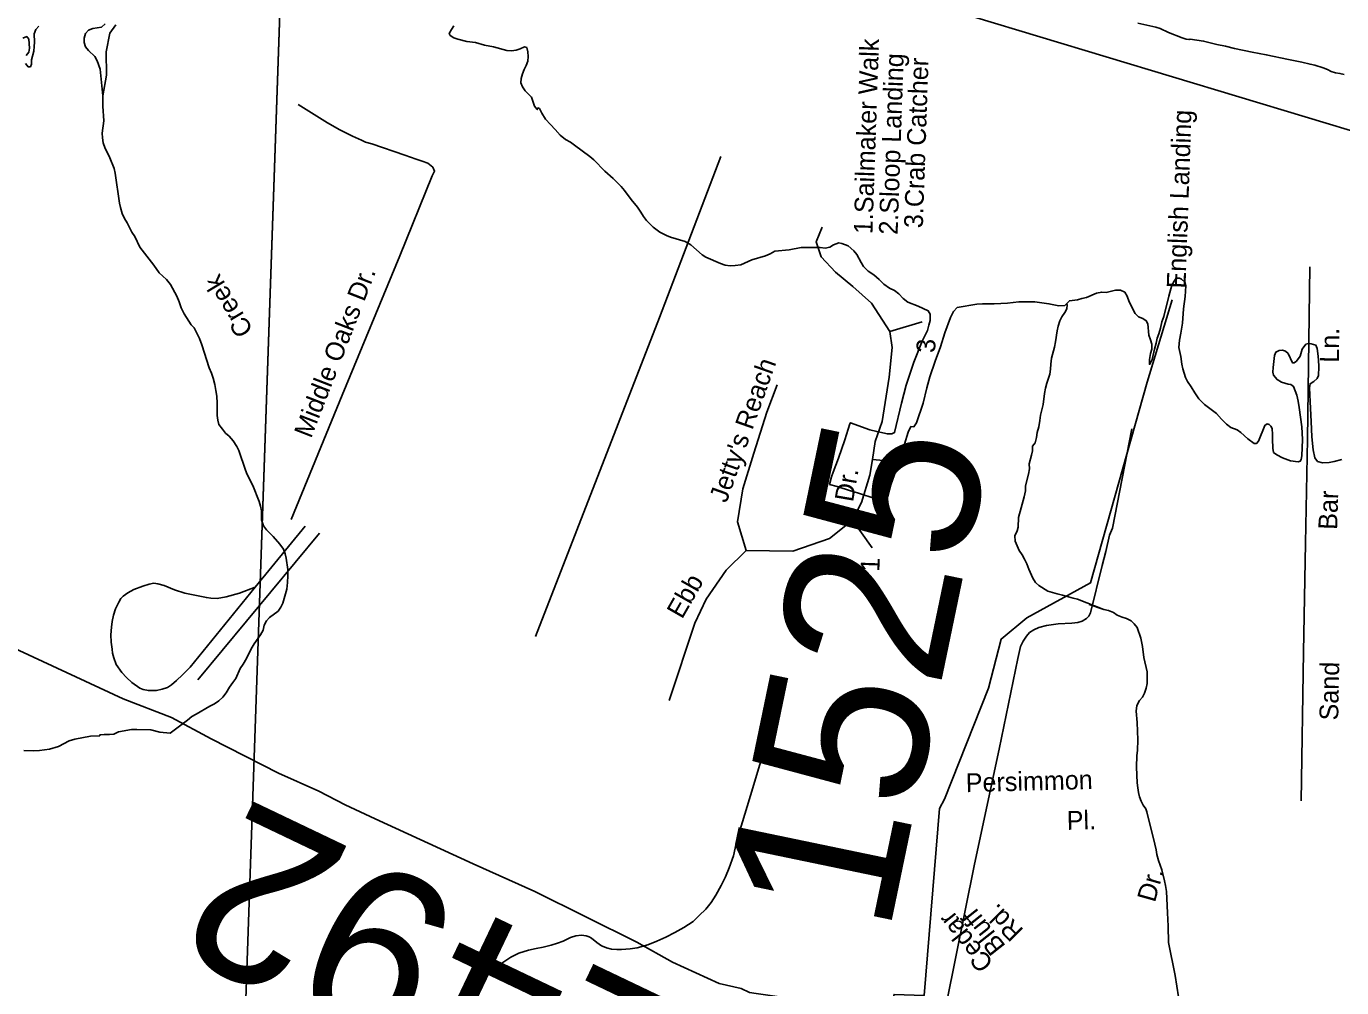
# Model space of a CAD drawing. Extents: x 2308163 to 2335412, y -96774 to 125428.
# Drawn here: x 2326033 to 2326126.4, y 123212.4 to 123280.7 of the extents above; entities that cross this region are included whole.
import ezdxf

# ---------------------------------------------------------------- set-up
doc = ezdxf.new("R2010")
doc.units = 0
for name, color, linetype in [('Old_Level_10', 7, 'Continuous'), ('Old_Level_21', 7, 'Continuous'), ('Old_Level_32', 7, 'Continuous'), ('Old_Level_35', 7, 'Continuous'), ('Old_Level_50', 7, 'Continuous'), ('Old_Level_59', 7, 'Continuous'), ('Old_Level_60', 7, 'Continuous'), ('Old_Level_61', 7, 'Continuous'), ('Old_Level_63', 7, 'Continuous'), ('Old_Level_8', 7, 'Continuous')]:
    doc.layers.add(name, color=color, linetype=linetype)

msp = doc.modelspace()

# ---------------------------------------------------------------- linework, layer by layer
at = {"layer": 'Old_Level_32'}
for points in [[(2326098.302, 123211.329), (2326100.302, 123221.192), (2326102.047, 123229.355), (2326103.38, 123235.79), (2326103.562, 123236.637), (2326103.76, 123237.018), (2326103.985, 123237.385), (2326104.197, 123237.64), (2326104.502, 123237.834), (2326104.855, 123237.989), (2326105.4, 123238.139), (2326106.239, 123238.249), (2326107.218, 123238.294), (2326107.631, 123238.343), (2326107.93, 123238.438), (2326108.242, 123238.639), (2326108.408, 123238.8), (2326108.54, 123239.04), (2326109.352, 123242.385), (2326109.62, 123243.386), (2326109.893, 123244.542), (2326110.104, 123245.039), (2326111.475, 123252.101)], [(2326024.035, 123240.511), (2326029.487, 123237.988), (2326032.481, 123236.361), (2326039.85, 123232.926)], [(2326039.85, 123232.926), (2326043.283, 123231.597), (2326046.116, 123230.094), (2326050.884, 123227.65), (2326053.752, 123226.388), (2326055.613, 123225.408), (2326057.739, 123224.419), (2326064.699, 123221.235), (2326069.083, 123219.252), (2326076.335, 123215.667), (2326078.862, 123214.252)], [(2326078.862, 123214.252), (2326082.17, 123212.726), (2326083.743, 123212.381), (2326084.315, 123212.102), (2326084.798, 123212.021), (2326086.295, 123211.817), (2326091.178, 123211.284), (2326094.057, 123211.281), (2326095.252, 123211.24)]]:
    msp.add_lwpolyline(points, dxfattribs=at)
at = {"layer": 'Old_Level_35'}
for p, q in [((2326052.788, 123245.192), (2326049.226, 123240.851)), ((2326045.168, 123234.282), (2326053.79, 123244.684))]:
    msp.add_line(p, q, dxfattribs=at)
for points in [[(2326051.779, 123245.667), (2326055.406, 123254.478), (2326059.506, 123264.378), (2326061.803, 123270.052), (2326061.968, 123270.373), (2326061.853, 123270.659), (2326061.499, 123270.95), (2326061.092, 123271.081), (2326060.651, 123271.219), (2326059.844, 123271.521), (2326057.508, 123272.309), (2326057.061, 123272.44), (2326056.781, 123272.572), (2326056.14, 123272.868), (2326055.251, 123273.303), (2326054.37, 123273.805), (2326052.291, 123275.114)], [(2326069.135, 123237.36), (2326077.941, 123259.987), (2326082.281, 123271.427)], [(2326078.622, 123232.814), (2326080.432, 123238.295), (2326081.245, 123240.002), (2326082.675, 123242.064), (2326084.081, 123243.448), (2326087.4, 123243.409), (2326089.996, 123244.3), (2326091.626, 123245.601), (2326092.273, 123246.861), (2326092.868, 123248.801), (2326093.058, 123249.925), (2326093.253, 123251.201), (2326093.754, 123252.616), (2326094.24, 123255.767), (2326094.464, 123257.87), (2326094.276, 123259.008), (2326092.987, 123261.013), (2326091.67, 123262.19), (2326090.422, 123263.213), (2326089.403, 123264.304), (2326089.063, 123265.371), (2326089.476, 123266.413)], [(2326123.486, 123225.688), (2326123.66, 123236.248), (2326123.808, 123243.969), (2326123.944, 123251.358), (2326124.116, 123263.59)], [(2326094.276, 123259.008), (2326096.586, 123259.687)], [(2326084.081, 123243.448), (2326083.472, 123245.505), (2326083.854, 123247.83), (2326084.621, 123250.367), (2326085.551, 123253.276), (2326086.297, 123255.211)], [(2326093.058, 123249.925), (2326094.875, 123249.75)], [(2326091.626, 123245.601), (2326093.033, 123243.659)], [(2326049.226, 123240.851), (2326044.617, 123235.192), (2326044.074, 123234.636), (2326043.656, 123234.241), (2326043.285, 123233.919), (2326043.013, 123233.738), (2326042.627, 123233.616), (2326042.214, 123233.528), (2326041.648, 123233.518), (2326041.288, 123233.603), (2326041.041, 123233.688), (2326040.479, 123234.085), (2326040.091, 123234.443), (2326039.763, 123234.808), (2326039.354, 123235.379), (2326039.185, 123235.851), (2326039.11, 123236.177), (2326039.082, 123236.463), (2326039.006, 123236.949), (2326038.99, 123237.469), (2326039.034, 123238.008), (2326039.085, 123238.415), (2326039.17, 123238.868), (2326039.314, 123239.315), (2326039.551, 123239.796), (2326039.697, 123240.064), (2326039.862, 123240.224), (2326040.194, 123240.459), (2326040.606, 123240.694), (2326041.264, 123240.924), (2326041.71, 123241.073), (2326042.036, 123241.141), (2326042.323, 123241.096), (2326042.763, 123240.965), (2326043.504, 123240.675), (2326044.231, 123240.439), (2326045.065, 123240.264), (2326045.765, 123240.114), (2326046.085, 123240.076), (2326046.525, 123240.064), (2326047.177, 123240.168), (2326048.122, 123240.432), (2326049.226, 123240.851)], [(2326085.54, 123229.815), (2326084.964, 123227.96), (2326084.564, 123226.625), (2326083.417, 123222.876), (2326083.189, 123221.782), (2326082.887, 123220.935), (2326082.624, 123220.294), (2326082.307, 123219.679), (2326081.944, 123219.011), (2326081.607, 123218.49), (2326081.23, 123218.008), (2326080.752, 123217.546), (2326080.315, 123217.138), (2326079.651, 123216.708), (2326079.02, 123216.345), (2326078.388, 123216.022), (2326077.737, 123215.726), (2326077.099, 123215.47), (2326076.36, 123215.266), (2326075.841, 123215.19), (2326075.228, 123215.147), (2326074.915, 123215.139), (2326074.536, 123215.164), (2326074.169, 123215.255), (2326073.996, 123215.334)], [(2326073.996, 123215.334), (2326073.821, 123215.413), (2326073.487, 123215.638), (2326073.113, 123215.949), (2326072.939, 123216.042), (2326072.732, 123216.114), (2326072.405, 123216.152), (2326071.999, 123216.124), (2326071.627, 123216.002), (2326071.095, 123215.733), (2326070.683, 123215.584), (2326070.244, 123215.449), (2326069.665, 123215.319), (2326069.173, 123215.21), (2326068.64, 123215.107), (2326067.955, 123214.884), (2326067.37, 123214.608), (2326066.746, 123214.172), (2326066.248, 123213.823), (2326065.917, 123213.542)]]:
    msp.add_lwpolyline(points, dxfattribs=at)
at = {"layer": 'Old_Level_50'}
msp.add_lwpolyline([(2326094.207, 123210.48), (2326094.59, 123211.958), (2326096.736, 123211.884), (2326097.816, 123225.143), (2326098.172, 123225.819), (2326101.298, 123233.695), (2326102.199, 123237.179), (2326104.009, 123238.679), (2326108.528, 123241.157), (2326112.565, 123255.395), (2326114.338, 123261.258)], dxfattribs=at)
at = {"layer": 'Old_Level_59'}
msp.add_line((2326113.092, 123222.623), (2326112.543, 123224.913), dxfattribs=at)
for points in [[(2326038.407, 123275.731), (2326038.405, 123274.994), (2326038.49, 123273.939), (2326038.365, 123273.085), (2326038.392, 123272.733), (2326038.447, 123272.391), (2326038.571, 123271.985), (2326038.766, 123271.628), (2326038.906, 123271.334), (2326039.22, 123270.576), (2326039.292, 123270.243), (2326039.607, 123268.098), (2326039.661, 123267.812), (2326039.782, 123267.376), (2326039.963, 123267.024), (2326040.151, 123266.707), (2326040.464, 123266.046), (2326040.682, 123265.754), (2326041.039, 123264.99), (2326042.036, 123263.711), (2326042.413, 123263.169), (2326042.927, 123262.694), (2326043.209, 123262.334), (2326043.677, 123261.51), (2326043.842, 123261.103), (2326043.976, 123260.681), (2326044.199, 123260.257), (2326044.684, 123259.468), (2326044.892, 123259.263), (2326045.281, 123258.507), (2326045.448, 123258.06), (2326045.971, 123256.431), (2326046.121, 123256.055), (2326046.249, 123255.679), (2326046.365, 123255.233), (2326046.448, 123254.809), (2326046.507, 123254.4), (2326046.531, 123253.912), (2326046.53, 123253.048), (2326046.567, 123252.711), (2326046.656, 123252.398), (2326046.906, 123252.059), (2326047.134, 123251.792), (2326047.383, 123251.57), (2326047.66, 123251.241), (2326047.925, 123250.85), (2326048.074, 123250.551), (2326048.538, 123249.163), (2326048.667, 123248.848), (2326049.069, 123248.067), (2326049.518, 123246.934), (2326049.612, 123246.61), (2326049.668, 123246.283), (2326049.672, 123245.628), (2326049.812, 123245.221), (2326050.034, 123244.929), (2326050.242, 123244.704), (2326050.513, 123244.45), (2326050.983, 123243.911), (2326051.238, 123243.551), (2326051.355, 123243.222), (2326051.434, 123242.915), (2326051.546, 123242.113), (2326051.548, 123241.671), (2326051.524, 123241.179), (2326051.466, 123240.713), (2326051.194, 123239.722), (2326051.05, 123239.447), (2326050.855, 123239.164), (2326050.248, 123238.697), (2326050.031, 123238.471), (2326049.865, 123238.162), (2326049.796, 123237.798), (2326049.612, 123237.474), (2326049.149, 123236.83), (2326048.946, 123236.481), (2326048.617, 123235.786), (2326048.386, 123235.398), (2326048.164, 123235.096), (2326047.847, 123234.375), (2326047.648, 123234.082), (2326047.403, 123233.77), (2326047.178, 123233.361), (2326046.923, 123233.045), (2326046.648, 123232.785), (2326046.346, 123232.582), (2326046.005, 123232.411), (2326045.036, 123231.835), (2326044.738, 123231.682), (2326044.43, 123231.419), (2326043.183, 123230.506)], [(2326106.827, 123260.968), (2326106.872, 123260.895), (2326106.856, 123260.616), (2326106.708, 123260.347), (2326106.501, 123260.039), (2326106.352, 123259.75), (2326106.236, 123259.388), (2326106.162, 123259.05), (2326106.053, 123258.266), (2326105.983, 123257.892), (2326105.773, 123257.107), (2326105.708, 123256.677), (2326105.69, 123256.327), (2326105.643, 123255.983), (2326105.43, 123255.346), (2326105.337, 123254.988), (2326105.267, 123254.609), (2326105.162, 123253.815), (2326104.985, 123253.059), (2326104.94, 123252.675), (2326104.866, 123252.24), (2326104.744, 123251.838), (2326104.689, 123251.479), (2326104.601, 123251.111), (2326104.418, 123250.858), (2326104.407, 123250.544), (2326104.343, 123250.231), (2326104.184, 123249.616), (2326104.196, 123249.255), (2326104.134, 123248.881), (2326103.911, 123248.051), (2326103.917, 123247.705), (2326103.835, 123247.271), (2326103.6, 123246.486), (2326103.422, 123245.806), (2326103.398, 123245.111), (2326103.333, 123244.854), (2326103.161, 123244.489), (2326103.179, 123244.128), (2326103.316, 123243.788), (2326103.478, 123243.467), (2326103.692, 123243.145), (2326103.859, 123242.844), (2326104.018, 123242.508), (2326104.155, 123242.128), (2326104.432, 123241.493), (2326104.625, 123241.182), (2326104.872, 123240.975), (2326105.493, 123240.562), (2326106.172, 123240.376), (2326106.551, 123240.297), (2326106.982, 123240.181), (2326107.297, 123240.073), (2326107.612, 123239.996), (2326109.483, 123239.266), (2326108.443, 123239.637)], [(2326109.483, 123239.266), (2326109.804, 123239.194), (2326110.157, 123239.055), (2326110.431, 123238.868), (2326110.792, 123238.728), (2326111.087, 123238.637), (2326111.413, 123238.478), (2326111.639, 123238.257), (2326111.843, 123237.986), (2326112.111, 123237.25), (2326112.218, 123236.636), (2326112.326, 123235.876), (2326112.552, 123234.852), (2326112.567, 123234.46), (2326112.554, 123234.013), (2326112.492, 123233.685), (2326112.366, 123233.344), (2326112.232, 123233.059), (2326112.011, 123232.823), (2326111.824, 123232.463), (2326111.783, 123232.048), (2326111.845, 123231.243), (2326111.885, 123230.012), (2326111.864, 123229.271), (2326111.823, 123228.911), (2326111.795, 123228.089), (2326111.856, 123226.964), (2326111.888, 123226.607), (2326111.946, 123226.275), (2326112.018, 123225.968), (2326112.134, 123225.669), (2326112.281, 123225.385), (2326112.459, 123225.124), (2326112.543, 123224.913)], [(2326043.183, 123230.506), (2326042.454, 123230.572), (2326041.817, 123230.741), (2326040.822, 123230.761), (2326040.458, 123230.753), (2326039.521, 123230.582), (2326039.199, 123230.43), (2326038.893, 123230.4), (2326038.513, 123230.408), (2326038.199, 123230.378), (2326038.199, 123230.312), (2326037.548, 123230.294), (2326036.424, 123230.074), (2326036.03, 123229.95), (2326035.269, 123229.56), (2326034.636, 123229.363), (2326033.925, 123229.256), (2326033.5, 123229.25), (2326032.811, 123229.269)], [(2326113.092, 123222.623), (2326113.19, 123222.218), (2326113.245, 123221.886), (2326113.355, 123221.46), (2326113.592, 123220.807), (2326113.795, 123220.028), (2326113.867, 123219.685), (2326113.917, 123219.261), (2326113.955, 123218.757), (2326114.011, 123217.739), (2326114.051, 123216.792), (2326114.063, 123215.644)], [(2326115.586, 123207.075), (2326115.468, 123209.731), (2326114.903, 123211.02), (2326114.544, 123213.29), (2326114.063, 123215.644)]]:
    msp.add_lwpolyline(points, dxfattribs=at)
at = {"layer": 'Old_Level_60'}
for points in [[(2326033.869, 123280.674), (2326033.653, 123280.427), (2326033.531, 123280.116), (2326033.556, 123279.541), (2326033.549, 123279.237), (2326033.505, 123278.898), (2326033.349, 123278.273), (2326033.361, 123277.968), (2326033.277, 123277.777), (2326033.105, 123277.783), (2326032.926, 123278.028)], [(2326038.407, 123275.731), (2326038.231, 123277.622), (2326038.01, 123278.214), (2326037.853, 123278.514), (2326037.386, 123278.931), (2326037.173, 123279.193), (2326037.083, 123279.506), (2326037.097, 123279.81), (2326037.177, 123280.138), (2326037.404, 123280.384), (2326037.701, 123280.511), (2326038.319, 123280.591), (2326038.569, 123280.827)], [(2326039.345, 123280.759), (2326038.92, 123280.164), (2326038.643, 123278.847), (2326038.666, 123277.195), (2326038.407, 123275.731)], [(2326076.607, 123267.477), (2326076.367, 123267.816), (2326075.916, 123268.36), (2326075.443, 123269.011), (2326075.204, 123269.279), (2326074.647, 123269.847), (2326074.065, 123270.375), (2326073.262, 123271.18), (2326072.986, 123271.418), (2326071.91, 123272.228), (2326071.622, 123272.426), (2326071.261, 123272.626), (2326070.893, 123272.923), (2326070.536, 123273.347), (2326070.19, 123273.689), (2326069.833, 123274.078), (2326069.587, 123274.483), (2326069.41, 123274.824), (2326069.302, 123274.868), (2326069.251, 123274.753), (2326069.052, 123274.999), (2326068.846, 123275.621), (2326068.639, 123275.852), (2326068.396, 123276.078), (2326068.201, 123276.355), (2326068.083, 123276.648), (2326068.113, 123276.957), (2326068.2, 123277.279), (2326068.329, 123277.595), (2326068.475, 123277.885), (2326068.583, 123278.186), (2326068.613, 123278.525), (2326068.585, 123278.846), (2326068.506, 123279.149), (2326068.342, 123279.21), (2326068.042, 123279.063), (2326067.754, 123278.966), (2326067.419, 123278.927), (2326067.101, 123278.948), (2326066.159, 123279.204), (2326065.512, 123279.328), (2326064.876, 123279.498), (2326064.251, 123279.59), (2326063.623, 123279.739), (2326063.325, 123279.841), (2326063.065, 123280.017), (2326063.013, 123280.156), (2326063.156, 123280.431), (2326063.326, 123280.699)], [(2326032.977, 123278.58), (2326033.155, 123278.828), (2326033.211, 123279.111), (2326033.16, 123279.753), (2326033.012, 123279.931), (2326032.732, 123279.808)], [(2326106.827, 123260.968), (2326106.701, 123260.845), (2326106.288, 123260.819), (2326105.577, 123260.965), (2326104.584, 123261.096), (2326103.457, 123261.115), (2326102.65, 123261.01), (2326101.691, 123260.957), (2326100.868, 123260.965), (2326100.452, 123260.929), (2326099.068, 123260.702), (2326098.815, 123260.416), (2326098.594, 123259.987), (2326098.194, 123258.908), (2326097.885, 123257.908), (2326097.517, 123256.899), (2326097.135, 123255.789), (2326096.916, 123254.994), (2326096.664, 123253.92), (2326096.177, 123252.525), (2326095.992, 123252.246), (2326095.785, 123252.253), (2326095.586, 123251.849), (2326095.337, 123251.004), (2326095.187, 123250.577), (2326095.017, 123249.973), (2326094.843, 123249.435), (2326094.354, 123248.116), (2326094.044, 123246.958), (2326093.293, 123247.131), (2326091.993, 123247.552), (2326091.502, 123247.686), (2326090.545, 123247.998), (2326090.004, 123248.154), (2326090.146, 123248.678), (2326090.257, 123249.019), (2326090.649, 123250.007), (2326091.09, 123251.303), (2326091.452, 123252.438), (2326091.5, 123252.528), (2326092.875, 123252.034), (2326093.354, 123251.9), (2326094.117, 123251.727), (2326094.434, 123251.741), (2326094.622, 123251.831), (2326095.107, 123253.923), (2326095.441, 123255.192), (2326095.997, 123256.814), (2326096.582, 123258.308), (2326096.958, 123259.083), (2326097.062, 123259.45), (2326097.142, 123259.778), (2326097.15, 123260.24), (2326097.012, 123260.478), (2326096.293, 123260.793), (2326095.561, 123261.077), (2326095.237, 123261.342), (2326094.915, 123261.684), (2326094.612, 123261.902), (2326094.275, 123262.087), (2326093.861, 123262.355), (2326093.527, 123262.692), (2326093.145, 123263.03), (2326092.751, 123263.288), (2326092.419, 123263.624), (2326092.25, 123263.905), (2326091.954, 123264.458), (2326091.732, 123264.735), (2326091.321, 123265.09), (2326090.89, 123265.257), (2326090.676, 123265.29), (2326090.285, 123265.161), (2326090.036, 123264.987), (2326089.702, 123264.917), (2326089.332, 123264.96), (2326089, 123264.972), (2326088.506, 123264.953), (2326087.996, 123264.956), (2326087.133, 123264.797), (2326086.134, 123264.705), (2326085.803, 123264.508), (2326085.468, 123264.372), (2326084.482, 123264.076), (2326083.712, 123263.742), (2326083.314, 123263.684), (2326082.943, 123263.667), (2326082.587, 123263.709), (2326082.268, 123263.822), (2326081.227, 123264.275), (2326080.966, 123264.436), (2326080.149, 123265.145), (2326079.759, 123265.382), (2326078.727, 123265.697), (2326078.424, 123265.804), (2326077.963, 123266.044), (2326077.495, 123266.395), (2326077.018, 123266.869), (2326076.808, 123267.161), (2326076.607, 123267.477)], [(2326106.827, 123260.968), (2326107.04, 123261.179), (2326107.601, 123261.256), (2326107.909, 123261.342), (2326108.247, 123261.412), (2326108.965, 123261.727), (2326109.327, 123261.796), (2326109.648, 123261.77), (2326110.314, 123261.93), (2326110.665, 123261.923), (2326110.963, 123261.786), (2326111.13, 123261.511), (2326111.283, 123261.104), (2326111.694, 123260.282), (2326111.931, 123260.045), (2326112.24, 123259.928), (2326112.487, 123259.762), (2326112.607, 123259.544), (2326112.681, 123258.749), (2326112.781, 123258.405), (2326112.897, 123258.096), (2326112.885, 123257.756), (2326112.797, 123257.444), (2326112.713, 123257.02), (2326112.719, 123256.664), (2326112.748, 123256.678), (2326112.916, 123257.003), (2326113.076, 123257.749), (2326113.196, 123258.177), (2326113.271, 123258.52), (2326113.383, 123258.826), (2326113.503, 123259.239), (2326113.6, 123259.683), (2326113.737, 123260.064), (2326114.092, 123261.51), (2326114.315, 123262.28), (2326114.549, 123262.688), (2326114.715, 123262.794), (2326114.853, 123262.785), (2326114.987, 123262.709), (2326115.228, 123262.507), (2326115.306, 123262.23), (2326115.263, 123261.475), (2326115.144, 123260.615), (2326115.064, 123259.586), (2326114.957, 123258.894), (2326114.848, 123258.395), (2326114.811, 123257.857), (2326114.936, 123257.218), (2326115.008, 123256.677), (2326115.092, 123256.344), (2326115.281, 123255.737), (2326115.413, 123255.443), (2326115.676, 123255.068), (2326115.936, 123254.643), (2326116.236, 123254.211), (2326116.625, 123253.826), (2326117.473, 123253.187), (2326117.841, 123252.773), (2326118.179, 123252.426), (2326118.504, 123252.181), (2326118.945, 123252.019), (2326119.199, 123251.837), (2326119.714, 123251.377), (2326120.15, 123251.052), (2326120.321, 123251.062), (2326120.466, 123251.224), (2326120.899, 123252.332), (2326121.065, 123252.444), (2326121.212, 123252.403), (2326121.341, 123252.292), (2326121.434, 123252.111), (2326121.46, 123251.683), (2326121.453, 123251.358), (2326121.478, 123250.732), (2326121.53, 123250.42), (2326121.766, 123250.255), (2326122.161, 123250.033), (2326122.739, 123249.825), (2326123.265, 123249.761), (2326123.422, 123249.806), (2326123.501, 123249.926), (2326123.528, 123250.174), (2326123.58, 123251.336), (2326123.532, 123252.231), (2326123.349, 123253.6), (2326123.277, 123254.049), (2326123.182, 123254.484), (2326122.952, 123255.102), (2326122.761, 123255.236), (2326122.559, 123255.273), (2326122.094, 123255.406), (2326121.778, 123255.59), (2326121.536, 123255.908), (2326121.489, 123256.118), (2326121.5, 123256.453), (2326121.595, 123257.303), (2326121.688, 123257.534), (2326121.922, 123257.648)], [(2326121.922, 123257.648), (2326122.17, 123257.67), (2326122.388, 123257.606), (2326122.575, 123257.432), (2326122.877, 123256.776), (2326123.002, 123256.787), (2326123.154, 123256.894), (2326123.416, 123257.24), (2326123.557, 123257.754), (2326123.828, 123258.11), (2326124.012, 123258.155), (2326124.199, 123258.133), (2326124.542, 123258.025), (2326124.63, 123257.793), (2326124.678, 123257.436), (2326124.716, 123256.992), (2326124.742, 123256.504), (2326124.723, 123255.884), (2326124.626, 123255.674), (2326124.385, 123255.454), (2326124.117, 123255.296), (2326124.076, 123254.997), (2326124.141, 123253.526), (2326124.199, 123252.61), (2326124.237, 123251.536), (2326124.331, 123250.608), (2326124.452, 123250.045), (2326124.652, 123249.784), (2326124.993, 123249.686), (2326125.471, 123249.705), (2326125.822, 123249.764), (2326126.386, 123249.913)]]:
    msp.add_lwpolyline(points, dxfattribs=at)
at = {"layer": 'Old_Level_61'}
msp.add_lwpolyline([(2326126.54, 123277.244), (2326126.242, 123277.31), (2326125.918, 123277.352), (2326125.627, 123277.448), (2326125.348, 123277.6), (2326125.057, 123277.712), (2326124.448, 123277.905), (2326124.124, 123277.967), (2326123.532, 123278.12), (2326122.599, 123278.294), (2326121.014, 123278.644), (2326120.022, 123278.825), (2326118.763, 123279.092), (2326118.116, 123279.257), (2326117.502, 123279.369), (2326116.566, 123279.615), (2326115.615, 123279.755), (2326115.532, 123279.712), (2326115.328, 123279.749), (2326115.033, 123279.846), (2326114.071, 123280.23), (2326113.48, 123280.494), (2326113.171, 123280.601), (2326111.904, 123280.889)], dxfattribs=at)
at = {"layer": 'Old_Level_63'}
msp.add_line((2326216.613, 123246.241), (2326051.481, 123296.047), dxfattribs=at)
for points in [[(2326051.48, 123296.017), (2326047.174, 123171.156), (2325940.967, 123174.819)], [(2326216.613, 123246.241), (2326207.405, 122979.252), (2326040.737, 122984.512), (2326051.481, 123296.047)]]:
    msp.add_lwpolyline(points, dxfattribs=at)

# ---------------------------------------------------------------- texts
at = {"layer": 'Old_Level_10'}
for s, height, rotation, p in [('1.Sailmaker Walk', 1.33284, 88.02472, (2326093.049, 123265.899)), ('2.Sloop Landing', 1.33284, 88.02472, (2326094.836, 123265.85)), ('3.Crab Catcher', 1.33284, 88.02472, (2326096.625, 123266.319)), ('English Landing', 1.33284, 88.02472, (2326115.275, 123262.037)), ('Middle Oaks Dr.', 1.33284, 68.76325, (2326053.195, 123251.364)), ('Ln.', 1.3328, 89.09894, (2326126.166, 123256.78)), ('3', 1.333, 88.02472, (2326097.503, 123257.468)), ("Jetty's Reach", 1.33284, 70.51059, (2326082.692, 123246.78)), ('2', 1.333, 88.02472, (2326096.562, 123249.653)), ('Dr.', 1.3328, 80.23905, (2326091.672, 123246.854)), ('Bar', 1.3328, 88.11968, (2326126.038, 123244.915)), ('1', 1.333, 88.02472, (2326093.541, 123241.944)), ('Ebb ', 1.3328, 60.32335, (2326079.537, 123238.54)), ('Sand', 1.3328, 88.91581, (2326126.116, 123231.391)), ('Persimmon ', 1.3328, 1.50763, (2326099.693, 123226.305)), ('Pl.', 1.3328, 1.50763, (2326106.862, 123223.631)), ('Dr.', 1.3328, 74.27871, (2326113.102, 123218.435)), ('Cedar ', 1.3328, 128.34841, (2326101.71, 123214.195)), ('Bluff', 1.3328, 128.34841, (2326102.559, 123215.396)), ('Rd.', 1.3328, 134.77371, (2326103.849, 123216.53))]:
    msp.add_text(s, height=height, rotation=rotation, dxfattribs=at).set_placement(p)
at = {"layer": 'Old_Level_21'}
msp.add_text('Creek', height=1.3328, rotation=121.14283, dxfattribs=at).set_placement((2326049.135, 123259.093))
at = {"layer": 'Old_Level_8'}
for s, rotation, p in [('1525', 78.27215, (2326094.182, 123216.046)), ('1492', 154.47922, (2326080.577, 123210.618))]:
    msp.add_text(s, height=11.9955, rotation=rotation, dxfattribs=at).set_placement(p)

doc.saveas('drawing.dxf')
